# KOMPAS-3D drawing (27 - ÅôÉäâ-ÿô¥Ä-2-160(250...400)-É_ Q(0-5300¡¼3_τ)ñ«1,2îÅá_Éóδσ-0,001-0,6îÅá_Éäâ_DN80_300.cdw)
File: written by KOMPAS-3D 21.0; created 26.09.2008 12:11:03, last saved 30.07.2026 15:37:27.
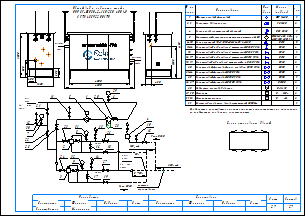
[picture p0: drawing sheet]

Sheets 1-2: A3, landscape

Document properties: Наименование: Макро:21; Автор: RaskoAdmin; Форматы листов документа: 2xA3; Полное имя файла: \\ur38nt01\Departments\КТО\КБ ПУРДГ\Заявки\Прайс-лист на типовые шкафы ГРПШ\ПУРДГ_стандарт_30_04_2026\ПУРДГ с РДГ(Н, В)\ПУРДГ-ШУЭО-2-160(250...400)-Р_ Q(0-5300нм3_ч)до1,2МПа_Рвых-0,001-0,6МПа_РДГ_DN80_300.cdw

Title block, sheet 1: Наименование: Пункт учета газа / ПУГ-Ш-400-Р / ЛГТИ.485922.001ТУ; designation: ЛГТИ.03.4411141; sheet number: 1; Количество листов документа: 2; organisation: ООО "ЭЛЬСТЕР Газэлектроника"; Форматы листов документа: A3; stored path: C:\Рабочие документы\Компас\ПУГ\Схема.cdw; Разработал: Устинов; Проверил: Кошкин; Утвердил: Кошкин
Title block, sheet 2: sheet number: 2; stored path: D:\Рабочие документы\Заявки\ПУРДГ\ПУРДГ-ШУЭО-2-100-Р 4411220.cdw; designation, second copy: ЛГТИ.03.4411141-

Views: Вид 1, Вид 2
Referenced files: wcvoit.frw
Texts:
  Normal
  № на
  схеме
  Усл.
  обозн.
  Марка
  (модель)
  Кол.
  Фильтр газовый фланцевый
  ФГ 16-80
  Регулятор давления газа
  РДГ-50
  Клапан предохранительный сбросной
  ПСК DN25
  Измерительный комплекс с ротационным счетчиком Ду50
  СГ-ЭК-Р-(0,2...2,0)-
  Кран кнопочный VE-РАСКО-НЗ-1,6-G1/2-М20
  DN15
  Кран шаровой "под приварку" штуцерный DN20 PN16
  Кран шаровой "под приварку" штуцерный DN25 PN16
  DN20
  DN25
  Кран шаровой "под приварку" штуцерный DN15 PN16
  Кран шаровой "под приварку" штуцерный п/п DN20 PN16
  Кран шаровой фланцевый с мех. приводом DN80 PN16
  Кран шаровой фланцевый DN50 PN16
  Кран шаровой фланцевый DN80 PN16
  Кран шаровой фланцевый DN300 PN16
  DN80
  DN50
  DN300
  Индикатор перепада давления
  Манометр
  Манометр-напоромер
  Электрообогреватель взрывозащищенный 2000Вт
  Delta 15
  0...     МПа
  0...     кПа
  Общий вид и габариты шкафа
  ПУРДГ-ШУЭО-2-160(250...400)-Р
  Выход газа
  Вход газа
  logo-rasko-ge.png
  DN 1
  местное
  сопротивление
  Римп DN20
  Выход
  газа
  Р=     кПа
  Вход
  Р=       МПа
  PDI
  Схема открывания дверей
  Предприятие изготовитель может заменять комплектующие на аналогичные,
  не ухудшающие заявленных характеристик.
  Должность
  Конструктор
  Фамилия
  Подпись
  Дата
  Согласовано
  Максимкин
  Лист
  Листов
  POLYLINE_STYLE_0.18_RGB_0_0_0
  POLYLINE_STYLE_0.50_RGB_0_0_0
  POLYLINE_STYLE_0.34_RGB_0_0_0
  PHANTOM_RGB_0_0_0_SC_1_THICK_0.18
  K5LT_THIN_RGB_0_0_0_THICK_0.18
  K5LT32769_RGB_0_0_0_THICK_0.18
  K5LT12_RGB_0_0_0_SC_1_THICK_0.18
  K5LT_DASHED_RGB_0_0_0_SC_1_THICK_0.18
  ACISOTGL_RGB_0_0_0_SC_0.8_THICK_0.25
  CONTINUOUS_RGB_0_127_31_THICK_0.3
  CONTINUOUS_RGB_0_0_255_THICK_0.35
  CONTINUOUS_RGB_255_0_0_THICK_0.35
  POLYLINE_STYLE_0.25_RGB_0_0_0
  CONTINUOUS_RGB_0_0_0_THICK_0.5
  POLYLINE_STYLE_0.35_RGB_0_0_255
  CONTINUOUS_RGB_0_0_0_THICK_0.4
  CONTINUOUS_RGB_0_0_0_THICK_0.35
  НЕВИДИМАЯ_RGB_0_0_0_SC_0.3_THICK_0.25
  СONTINUOUS_RGB_0_0_0_THICK_0.25
  ОСЕВАЯ2_RGB_248_153_30_SC_0.3_THICK_0.25
  Без оформления
Dimensions and other numbers on the sheet: 1; 2, 3; 2; 4; 5; -160 (250; 400)/1,6; 6-10; 11-14; 15; 16, 17; 18, 19; 20; 21-24; 25; 26, 27; 28; 29, 30; 31, 32; 33; 1500; 450; 600; 1200; 550; 305; 4000; 4130; 2000; 4300; 5,,,7DN 1; 7; 30; 12; 21; 22; 11; 6; 29; 23; 31; 8; 13; 26; 18; 10; 24; 32; 9; 3; 14; 27; 19; 16; 17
